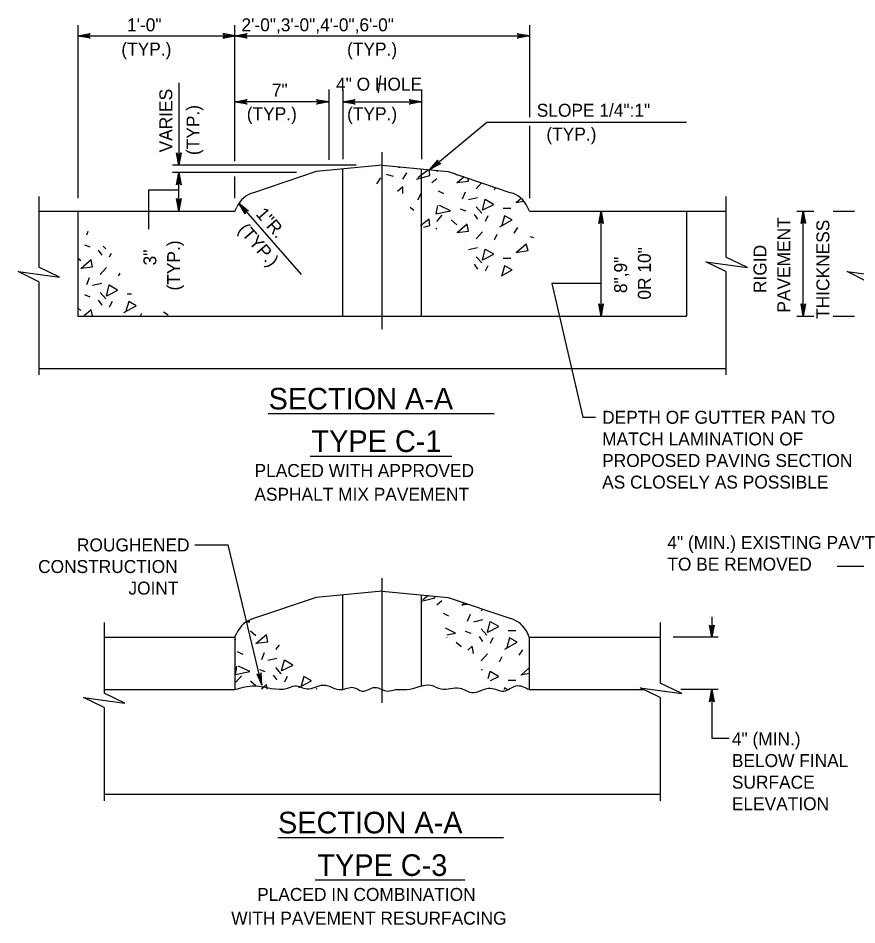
# Model space of a CAD drawing. Extents: x -28.1 to -20.9, y 67 to 77.1.
# Drawn here: x -28.051 to -24.167, y 72.946 to 77.144 of the extents above; entities that cross this region are included whole.
import ezdxf

# ---------------------------------------------------------------- set-up
doc = ezdxf.new("R2010")
doc.units = 0
for name, color, linetype in [('DETL-DIMS', 7, 'Continuous'), ('DETL-LINE', 7, 'Continuous'), ('DETL-NOTE', 7, 'Continuous'), ('DETL-PATT', 7, 'Continuous'), ('DETL-TITL', 7, 'Continuous')]:
    doc.layers.add(name, color=color, linetype=linetype)

msp = doc.modelspace()

# ---------------------------------------------------------------- linework, layer by layer
at = {"layer": 'DETL-DIMS'}
for p, q in [((-27.7744, 77.1109), (-27.7744, 76.3101)), ((-27.0471, 76.4812), (-27.0471, 77.1109)), ((-25.6837, 77.1109), (-25.6837, 76.6848)), ((-27.7744, 77.0612), (-27.0471, 77.0612)), ((-27.0471, 77.0612), (-25.6837, 77.0612)), ((-27.3076, 76.8447), (-27.3076, 76.463)), ((-26.6127, 76.8138), (-26.6127, 76.4872)), ((-26.5472, 76.8138), (-26.5472, 76.4909)), ((-26.1836, 76.8138), (-26.1836, 76.4909)), ((-26.6127, 76.7557), (-27.0471, 76.7557)), ((-26.5472, 76.7557), (-26.1836, 76.7557)), ((-26.1447, 76.4426), (-25.8808, 76.6621)), ((-25.8808, 76.6621), (-24.9559, 76.6621)), ((-25.6837, 76.6457), (-25.6837, 76.3101)), ((-26.3654, 75.704), (-26.3654, 76.5236)), ((-26.4866, 76.463), (-27.3369, 76.463)), ((-26.7619, 76.4285), (-27.3369, 76.4285)), ((-27.3066, 76.2522), (-27.3066, 76.4285)), ((-27.0471, 76.3101), (-27.0471, 76.4104)), ((-27.4468, 76.1665), (-27.4468, 76.3488)), ((-27.4468, 76.3488), (-27.3066, 76.3488)), ((-27.0289, 76.2867), (-26.7405, 75.9569)), ((-25.3519, 75.7646), (-25.3519, 76.2495)), ((-24.4455, 76.2495), (-24.3665, 76.2495)), ((-24.4152, 75.7646), (-24.4152, 76.2495)), ((-24.2764, 76.2495), (-24.1781, 76.2495)), ((-25.3523, 75.9158), (-25.58, 75.9158)), ((-25.58, 75.9158), (-25.436, 75.2959)), ((-24.4455, 75.7646), (-24.3665, 75.7646)), ((-24.2764, 75.7646), (-24.1781, 75.7646)), ((-25.436, 75.2959), (-25.3776, 75.2958)), ((-27.2325, 74.7049), (-27.0788, 74.7049)), ((-26.9226, 74.0556), (-27.0788, 74.7049)), ((-24.1259, 74.6053), (-24.2583, 74.6053)), ((-26.3659, 73.9746), (-26.3659, 74.5518)), ((-24.8393, 74.3726), (-24.8393, 74.2777)), ((-24.809, 74.2777), (-25.0175, 74.2777)), ((-24.809, 74.0352), (-24.9825, 74.0352)), ((-24.8393, 74.0352), (-24.8393, 73.8104)), ((-24.8393, 73.8104), (-24.7588, 73.8104))]:
    msp.add_line(p, q, dxfattribs=at)
for points in [[(-27.7744, 77.0612), (-27.7179, 77.0718), (-27.7223, 77.0688), (-27.7245, 77.065), (-27.7252, 77.0612), (-27.7245, 77.0574), (-27.7223, 77.0536), (-27.7179, 77.0506), (-27.7744, 77.0612), (-27.7223, 77.0536), (-27.7245, 77.0574), (-27.7744, 77.0612), (-27.7252, 77.0612), (-27.7245, 77.065), (-27.7744, 77.0612), (-27.7223, 77.0688)], [(-27.0471, 77.0612), (-27.1036, 77.0718), (-27.0993, 77.0688), (-27.097, 77.065), (-27.0964, 77.0612), (-27.097, 77.0574), (-27.0993, 77.0536), (-27.1036, 77.0506), (-27.0471, 77.0612), (-27.0993, 77.0536), (-27.097, 77.0574), (-27.0471, 77.0612), (-27.0964, 77.0612), (-27.097, 77.065), (-27.0471, 77.0612), (-27.0993, 77.0688)], [(-27.0471, 77.0612), (-26.9907, 77.0718), (-26.995, 77.0688), (-26.9972, 77.065), (-26.9979, 77.0612), (-26.9972, 77.0574), (-26.995, 77.0536), (-26.9907, 77.0506), (-27.0471, 77.0612), (-26.995, 77.0536), (-26.9972, 77.0574), (-27.0471, 77.0612), (-26.9979, 77.0612), (-26.9972, 77.065), (-27.0471, 77.0612), (-26.995, 77.0688)], [(-25.6837, 77.0612), (-25.7402, 77.0506), (-25.7358, 77.0536), (-25.7336, 77.0574), (-25.7329, 77.0612), (-25.7336, 77.065), (-25.7358, 77.0688), (-25.7402, 77.0718), (-25.6837, 77.0612), (-25.7358, 77.0688), (-25.7336, 77.065), (-25.6837, 77.0612), (-25.7329, 77.0612), (-25.7336, 77.0574), (-25.6837, 77.0612), (-25.7358, 77.0536)], [(-27.0471, 76.7557), (-26.9907, 76.7663), (-26.995, 76.7632), (-26.9972, 76.7595), (-26.9979, 76.7557), (-26.9972, 76.7519), (-26.995, 76.7481), (-26.9907, 76.7451), (-27.0471, 76.7557), (-26.995, 76.7481), (-26.9972, 76.7519), (-27.0471, 76.7557), (-26.9979, 76.7557), (-26.9972, 76.7595), (-27.0471, 76.7557), (-26.995, 76.7632)], [(-26.6127, 76.7557), (-26.6691, 76.7451), (-26.6648, 76.7481), (-26.6625, 76.7519), (-26.6619, 76.7557), (-26.6625, 76.7595), (-26.6648, 76.7632), (-26.6691, 76.7663), (-26.6127, 76.7557), (-26.6648, 76.7632), (-26.6625, 76.7595), (-26.6127, 76.7557), (-26.6619, 76.7557), (-26.6625, 76.7519), (-26.6127, 76.7557), (-26.6648, 76.7481)], [(-26.5472, 76.7557), (-26.4907, 76.7663), (-26.4951, 76.7632), (-26.4974, 76.7595), (-26.498, 76.7557), (-26.4974, 76.7519), (-26.4951, 76.7481), (-26.4907, 76.7451), (-26.5472, 76.7557), (-26.4951, 76.7481), (-26.4974, 76.7519), (-26.5472, 76.7557), (-26.498, 76.7557), (-26.4974, 76.7595), (-26.5472, 76.7557), (-26.4951, 76.7632)], [(-26.1836, 76.7557), (-26.2401, 76.7451), (-26.2357, 76.7481), (-26.2335, 76.7519), (-26.2329, 76.7557), (-26.2335, 76.7595), (-26.2357, 76.7632), (-26.2401, 76.7663), (-26.1836, 76.7557), (-26.2357, 76.7632), (-26.2335, 76.7595), (-26.1836, 76.7557), (-26.2329, 76.7557), (-26.2335, 76.7519), (-26.1836, 76.7557), (-26.2357, 76.7481)], [(-27.3076, 76.463), (-27.3182, 76.5195), (-27.3152, 76.5151), (-27.3114, 76.5129), (-27.3076, 76.5122), (-27.3038, 76.5129), (-27.3, 76.5151), (-27.297, 76.5195), (-27.3076, 76.463), (-27.3, 76.5151), (-27.3038, 76.5129), (-27.3076, 76.463), (-27.3076, 76.5122), (-27.3114, 76.5129), (-27.3076, 76.463), (-27.3152, 76.5151)], [(-26.1447, 76.4426), (-26.1081, 76.4869), (-26.1095, 76.4818), (-26.1088, 76.4774), (-26.1069, 76.4741), (-26.1039, 76.4716), (-26.0998, 76.4701), (-26.0945, 76.4706), (-26.1447, 76.4426), (-26.0998, 76.4701), (-26.1039, 76.4716), (-26.1447, 76.4426), (-26.1069, 76.4741), (-26.1088, 76.4774), (-26.1447, 76.4426), (-26.1095, 76.4818)], [(-27.3066, 76.4285), (-27.296, 76.372), (-27.2991, 76.3764), (-27.3029, 76.3787), (-27.3066, 76.3793), (-27.3104, 76.3787), (-27.3142, 76.3764), (-27.3172, 76.372), (-27.3066, 76.4285), (-27.3142, 76.3764), (-27.3104, 76.3787), (-27.3066, 76.4285), (-27.3066, 76.3793), (-27.3029, 76.3787), (-27.3066, 76.4285), (-27.2991, 76.3764)], [(-27.3066, 76.2522), (-27.3172, 76.3087), (-27.3142, 76.3043), (-27.3104, 76.3021), (-27.3066, 76.3014), (-27.3029, 76.3021), (-27.2991, 76.3043), (-27.296, 76.3087), (-27.3066, 76.2522), (-27.2991, 76.3043), (-27.3029, 76.3021), (-27.3066, 76.2522), (-27.3066, 76.3014), (-27.3104, 76.3021), (-27.3066, 76.2522), (-27.3142, 76.3043)], [(-27.0289, 76.2867), (-26.9838, 76.2512), (-26.9889, 76.2525), (-26.9932, 76.2517), (-26.9965, 76.2497), (-26.9989, 76.2467), (-27.0003, 76.2425), (-26.9997, 76.2372), (-27.0289, 76.2867), (-27.0003, 76.2425), (-26.9989, 76.2467), (-27.0289, 76.2867), (-26.9965, 76.2497), (-26.9932, 76.2517), (-27.0289, 76.2867), (-26.9889, 76.2525)], [(-25.3519, 76.2495), (-25.3414, 76.193), (-25.3444, 76.1974), (-25.3481, 76.1996), (-25.3519, 76.2003), (-25.3557, 76.1996), (-25.3595, 76.1974), (-25.3625, 76.193), (-25.3519, 76.2495), (-25.3595, 76.1974), (-25.3557, 76.1996), (-25.3519, 76.2495), (-25.3519, 76.2003), (-25.3481, 76.1996), (-25.3519, 76.2495), (-25.3444, 76.1974)], [(-24.4152, 76.2495), (-24.4046, 76.193), (-24.4076, 76.1974), (-24.4114, 76.1996), (-24.4152, 76.2003), (-24.419, 76.1996), (-24.4228, 76.1974), (-24.4258, 76.193), (-24.4152, 76.2495), (-24.4228, 76.1974), (-24.419, 76.1996), (-24.4152, 76.2495), (-24.4152, 76.2003), (-24.4114, 76.1996), (-24.4152, 76.2495), (-24.4076, 76.1974)], [(-25.3519, 75.7646), (-25.3625, 75.8211), (-25.3595, 75.8168), (-25.3557, 75.8145), (-25.3519, 75.8139), (-25.3481, 75.8145), (-25.3444, 75.8168), (-25.3414, 75.8211), (-25.3519, 75.7646), (-25.3444, 75.8168), (-25.3481, 75.8145), (-25.3519, 75.7646), (-25.3519, 75.8139), (-25.3557, 75.8145), (-25.3519, 75.7646), (-25.3595, 75.8168)], [(-24.4152, 75.7646), (-24.4258, 75.8211), (-24.4228, 75.8168), (-24.419, 75.8145), (-24.4152, 75.8139), (-24.4114, 75.8145), (-24.4076, 75.8168), (-24.4046, 75.8211), (-24.4152, 75.7646), (-24.4076, 75.8168), (-24.4114, 75.8145), (-24.4152, 75.7646), (-24.4152, 75.8139), (-24.419, 75.8145), (-24.4152, 75.7646), (-24.4228, 75.8168)], [(-24.8393, 74.2777), (-24.8499, 74.3341), (-24.8469, 74.3298), (-24.8431, 74.3275), (-24.8393, 74.3269), (-24.8355, 74.3275), (-24.8317, 74.3298), (-24.8287, 74.3341), (-24.8393, 74.2777), (-24.8317, 74.3298), (-24.8355, 74.3275), (-24.8393, 74.2777), (-24.8393, 74.3269), (-24.8431, 74.3275), (-24.8393, 74.2777), (-24.8469, 74.3298)], [(-26.9226, 74.0556), (-26.9255, 74.113), (-26.9274, 74.1081), (-26.9306, 74.105), (-26.9341, 74.1035), (-26.9379, 74.1033), (-26.9421, 74.1046), (-26.9461, 74.1081), (-26.9226, 74.0556), (-26.9421, 74.1046), (-26.9379, 74.1033), (-26.9226, 74.0556), (-26.9341, 74.1035), (-26.9306, 74.105), (-26.9226, 74.0556), (-26.9274, 74.1081)], [(-24.8393, 74.0352), (-24.8287, 73.9788), (-24.8317, 73.9831), (-24.8355, 73.9853), (-24.8393, 73.986), (-24.8431, 73.9853), (-24.8469, 73.9831), (-24.8499, 73.9788), (-24.8393, 74.0352), (-24.8469, 73.9831), (-24.8431, 73.9853), (-24.8393, 74.0352), (-24.8393, 73.986), (-24.8355, 73.9853), (-24.8393, 74.0352), (-24.8317, 73.9831)]]:
    msp.add_lwpolyline(points, dxfattribs=at)
at = {"layer": 'DETL-LINE'}
for p, q in [((-26.3654, 76.463), (-26.671, 76.4335)), ((-26.5472, 75.7646), (-26.5472, 76.4455)), ((-26.3654, 76.463), (-26.0599, 76.4335)), ((-26.1836, 75.7646), (-26.1836, 76.4455)), ((-26.671, 76.4335), (-26.961, 76.3355)), ((-26.0599, 76.4335), (-25.7699, 76.3355)), ((-27.9562, 76.3178), (-27.9562, 75.9902)), ((-24.7746, 76.3178), (-24.7746, 76.0374)), ((-27.9562, 76.2495), (-27.0471, 76.2495)), ((-27.7744, 76.2495), (-27.7744, 75.7646)), ((-27.0471, 76.2495), (-27.0382, 76.2691)), ((-25.6837, 76.2495), (-25.6926, 76.2691)), ((-25.6837, 76.2495), (-24.7746, 76.2495)), ((-24.9564, 76.2495), (-24.9564, 75.7646)), ((-24.7746, 75.9708), (-24.7746, 75.4923)), ((-27.9562, 75.9236), (-27.9562, 75.4923)), ((-27.7744, 75.7646), (-24.9564, 75.7646)), ((-27.9562, 75.5222), (-24.7746, 75.5222)), ((-26.3659, 74.4911), (-26.6715, 74.4617)), ((-26.5477, 74.0354), (-26.5477, 74.4736)), ((-26.3659, 74.4911), (-26.0604, 74.4617)), ((-26.1841, 74.0489), (-26.1841, 74.4736)), ((-26.6715, 74.4617), (-26.9615, 74.3637)), ((-26.0604, 74.4617), (-25.7704, 74.3637)), ((-27.6537, 74.346), (-27.6537, 74.0183)), ((-25.0781, 74.346), (-25.0781, 74.0655)), ((-27.6537, 74.2777), (-27.0476, 74.2777)), ((-27.0476, 74.2777), (-27.0388, 74.2972)), ((-27.0476, 74.2777), (-27.0476, 74.0352)), ((-25.6842, 74.2777), (-25.6931, 74.2972)), ((-25.6842, 74.2777), (-25.0781, 74.2777)), ((-25.6842, 74.2777), (-25.6842, 74.0352)), ((-27.6537, 74.0352), (-27.0476, 74.0352)), ((-25.6842, 74.0352), (-25.1522, 74.0352)), ((-25.0781, 73.999), (-25.0781, 73.5205)), ((-27.6537, 73.9517), (-27.6537, 73.5205)), ((-27.6537, 73.5504), (-25.0781, 73.5504))]:
    msp.add_line(p, q, dxfattribs=at)
for points in [[(-24.7746, 75.9708), (-24.8665, 76.0158), (-24.6743, 75.9896), (-24.7746, 76.0374)], [(-27.9562, 75.9236), (-28.0514, 75.9701), (-27.8592, 75.944), (-27.9562, 75.9902)], [(-24.1175, 75.9236), (-24.2126, 75.9701), (-24.0204, 75.944), (-24.1175, 75.9902)], [(-25.0781, 73.999), (-25.17, 74.0439), (-24.9778, 74.0178), (-25.0781, 74.0655)], [(-27.6537, 73.9517), (-27.7488, 73.9983), (-27.5566, 73.9722), (-27.6537, 74.0183)]]:
    msp.add_lwpolyline(points, dxfattribs=at)
for centre, start, end in [((-26.9279, 76.2189), 105.8409, 155.576), ((-25.803, 76.2189), 24.424, 74.1591), ((-26.9284, 74.2471), 105.8409, 155.576), ((-25.8034, 74.2471), 24.424, 74.1591)]:
    msp.add_arc(centre, 0.1212, start, end, dxfattribs=at)
msp.add_spline([(-27.0476, 74.0352), (-26.9555, 74.0524), (-26.8035, 74.042), (-26.769, 74.0524), (-26.7137, 74.0386), (-26.6377, 74.0559), (-26.5548, 74.0351), (-26.4996, 74.0455), (-26.4581, 74.0282), (-26.3994, 74.0455), (-26.3407, 74.0282), (-26.3027, 74.0351), (-26.2509, 74.0351), (-26.1404, 74.0559), (-26.092, 74.0386), (-26.0057, 74.042), (-25.9504, 74.0213), (-25.8641, 74.042), (-25.8019, 74.0282), (-25.7466, 74.0524), (-25.6842, 74.0352)], degree=3, dxfattribs=at)
at = {"layer": 'DETL-NOTE'}
msp.add_line((-26.3825, 76.7977), (-26.372, 76.8781), dxfattribs=at)
at = {"layer": 'DETL-PATT'}
for p, q in [((-26.4436, 76.4436), (-26.445, 76.4425)), ((-26.2895, 76.4533), (-26.2822, 76.4539)), ((-26.2822, 76.4539), (-26.2822, 76.4539)), ((-26.373, 76.4051), (-26.3922, 76.3762)), ((-26.3473, 76.4212), (-26.3152, 76.4115)), ((-26.2703, 76.3987), (-26.251, 76.4276)), ((-26.1355, 76.3827), (-26.113, 76.4019)), ((-26.113, 76.434), (-26.1094, 76.4381)), ((-26.0239, 76.4214), (-26.02, 76.418)), ((-25.9053, 76.3813), (-25.9301, 76.3538)), ((-25.8406, 76.3595), (-25.8467, 76.3474)), ((-26.1997, 76.3024), (-26.1836, 76.3345)), ((-26.1066, 76.3442), (-26.0809, 76.3313)), ((-25.9815, 76.3377), (-25.9943, 76.3057)), ((-25.9237, 76.3121), (-25.9654, 76.3024)), ((-26.2366, 76.2685), (-26.2189, 76.2543)), ((-26.113, 76.2029), (-26.0874, 76.2318)), ((-26.0039, 76.2607), (-25.9782, 76.2511)), ((-25.9398, 76.235), (-25.9237, 76.2126)), ((-25.9301, 76.2703), (-25.9044, 76.2415)), ((-25.805, 76.2639), (-25.7697, 76.2639)), ((-26.0456, 76.2094), (-26.02, 76.1869)), ((-25.8756, 76.2286), (-25.8884, 76.2029)), ((-27.7288, 76.1556), (-27.7351, 76.1397)), ((-26.1165, 76.1679), (-26.113, 76.1709)), ((-25.9012, 76.1548), (-25.9301, 76.1227)), ((-25.7536, 76.1484), (-25.7376, 76.1741)), ((-25.9815, 76.1067), (-25.9817, 76.1062)), ((-25.8338, 76.142), (-25.8467, 76.1163)), ((-25.6798, 76.1323), (-25.665, 76.1281)), ((-27.7447, 76.0948), (-27.7191, 76.0852)), ((-27.6806, 76.0691), (-27.6645, 76.0467)), ((-27.6568, 76.0885), (-27.6453, 76.0755)), ((-25.9237, 76.081), (-25.9654, 76.0714)), ((-27.7744, 76.0329), (-27.7608, 76.021)), ((-27.6209, 76.0536), (-27.6292, 76.037)), ((-25.9301, 76.0393), (-25.9044, 76.0104)), ((-25.805, 76.0329), (-25.7697, 76.0329)), ((-27.642, 75.9889), (-27.6709, 75.9568)), ((-25.9398, 76.004), (-25.9237, 75.9815)), ((-25.8756, 75.9976), (-25.8884, 75.9719)), ((-27.7223, 75.9408), (-27.7351, 75.9087)), ((-27.5808, 75.9637), (-27.5875, 75.9504)), ((-27.6645, 75.9151), (-27.7062, 75.9054)), ((-27.7447, 75.8637), (-27.7191, 75.8541)), ((-27.6709, 75.8734), (-27.6453, 75.8445)), ((-27.5458, 75.8669), (-27.5257, 75.8669)), ((-27.6806, 75.838), (-27.6645, 75.8156)), ((-27.6164, 75.8316), (-27.6292, 75.806)), ((-27.7744, 75.8018), (-27.7608, 75.7899)), ((-27.4854, 75.7659), (-27.4784, 75.7771)), ((-27.3789, 75.7835), (-27.3564, 75.7707)), ((-26.1124, 74.4282), (-26.0899, 74.4474)), ((-26.0835, 74.3896), (-26.0579, 74.3768)), ((-25.9584, 74.3832), (-25.9712, 74.3511)), ((-25.8997, 74.4074), (-25.907, 74.3993)), ((-25.9006, 74.3576), (-25.9423, 74.3479)), ((-26.9756, 74.3076), (-26.9499, 74.2851)), ((-25.9808, 74.3062), (-25.9552, 74.2966)), ((-25.907, 74.3158), (-25.8814, 74.287)), ((-25.7819, 74.3094), (-25.7466, 74.3094)), ((-27.0476, 74.2651), (-27.043, 74.2691)), ((-26.0648, 74.2767), (-26.0643, 74.2773)), ((-25.9166, 74.2805), (-25.9006, 74.2581)), ((-25.8525, 74.2741), (-25.8653, 74.2484)), ((-26.8421, 74.2408), (-26.8601, 74.2209)), ((-26.0226, 74.2549), (-25.9991, 74.2343)), ((-25.7305, 74.1939), (-25.7145, 74.2196)), ((-27.0366, 74.2113), (-27.0109, 74.1985)), ((-26.9114, 74.2049), (-26.9243, 74.1728)), ((-26.8536, 74.1792), (-26.8954, 74.1696)), ((-25.8781, 74.2003), (-25.907, 74.1682)), ((-25.8107, 74.1875), (-25.8236, 74.1618)), ((-26.8601, 74.1375), (-26.8344, 74.1086)), ((-27.043, 74.0701), (-27.0173, 74.099)), ((-26.9339, 74.1279), (-26.9082, 74.1182)), ((-26.8697, 74.1022), (-26.8536, 74.0797)), ((-26.8055, 74.0958), (-26.8184, 74.0701)), ((-25.9006, 74.1265), (-25.9067, 74.1251)), ((-26.9756, 74.0765), (-26.9499, 74.054)), ((-25.7819, 74.0784), (-25.7466, 74.0784)), ((-26.6703, 74.0367), (-26.6675, 74.0412))]:
    msp.add_line(p, q, dxfattribs=at)
for points in [[(-26.2061, 76.3987), (-26.1451, 76.4148), (-26.1481, 76.4416)], [(-26.1507, 76.4419), (-26.1997, 76.4051)], [(-25.9862, 76.4087), (-26.02, 76.3795)], [(-26.02, 76.3827), (-25.9654, 76.3891), (-25.9681, 76.4025)], [(-26.2703, 76.3316), (-26.2703, 76.3634), (-26.2939, 76.3412)], [(-26.1098, 76.2768), (-26.1163, 76.2383), (-26.0489, 76.2511), (-26.1002, 76.2768)], [(-25.8499, 76.28), (-25.9012, 76.2543), (-25.8884, 76.3057), (-25.8499, 76.2832)], [(-25.7472, 76.2896), (-25.7112, 76.2956)], [(-25.7221, 76.3083), (-25.744, 76.2896)], [(-26.1726, 76.1765), (-26.1451, 76.1837), (-26.1483, 76.2126), (-26.1886, 76.1824)], [(-26.02, 76.1516), (-25.9654, 76.158), (-25.9718, 76.1901), (-26.0186, 76.1495)], [(-25.821, 76.1773), (-25.7632, 76.2094), (-25.7985, 76.2286), (-25.8114, 76.1837)], [(-25.8499, 76.0489), (-25.9012, 76.0232), (-25.8884, 76.0746), (-25.8499, 76.0521)], [(-25.7472, 76.0585), (-25.6894, 76.0682), (-25.6991, 76.097), (-25.744, 76.0585)], [(-27.7608, 75.9857), (-27.7062, 75.9921), (-27.7126, 76.0242), (-27.7608, 75.9825)], [(-25.8124, 75.951), (-25.7632, 75.9783), (-25.7985, 75.9976), (-25.8114, 75.9526)], [(-25.8124, 75.951), (-25.8124, 75.951)], [(-27.5907, 75.883), (-27.642, 75.8573), (-27.6292, 75.9087), (-27.5907, 75.8862)], [(-27.5618, 75.7803), (-27.5041, 75.8124), (-27.5394, 75.8316), (-27.5522, 75.7867)], [(-27.707, 75.7649), (-27.7126, 75.7931), (-27.7454, 75.7648)], [(-26.183, 74.4442), (-26.122, 74.4603), (-26.1229, 74.4677)], [(-26.1503, 74.4703), (-26.1766, 74.4506)], [(-25.9842, 74.436), (-25.9969, 74.425)], [(-25.9969, 74.4282), (-25.9703, 74.4313)], [(-27.001, 74.3451), (-26.9788, 74.3493), (-26.9881, 74.354)], [(-25.8268, 74.3255), (-25.8781, 74.2998), (-25.8653, 74.3511), (-25.8268, 74.3287)], [(-26.0662, 74.2889), (-26.0258, 74.2966), (-26.0726, 74.32)], [(-25.7241, 74.3351), (-25.7217, 74.3355)], [(-26.9499, 74.2498), (-26.8954, 74.2562), (-26.9018, 74.2883), (-26.9499, 74.2466)], [(-25.7979, 74.2228), (-25.7401, 74.2549), (-25.7755, 74.2741), (-25.7883, 74.2292)], [(-25.9458, 74.2031), (-25.9423, 74.2035), (-25.9488, 74.2356), (-25.9689, 74.2181)], [(-26.7798, 74.1471), (-26.8312, 74.1214), (-26.8184, 74.1728), (-26.7798, 74.1503)], [(-27.0398, 74.1439), (-27.0462, 74.1054), (-26.9788, 74.1182), (-27.0301, 74.1439)], [(-25.6842, 74.1355), (-25.7209, 74.104)], [(-26.751, 74.0444), (-26.6932, 74.0765), (-26.7285, 74.0958), (-26.7413, 74.0508)], [(-25.8739, 74.0858), (-25.8653, 74.1201), (-25.8268, 74.0976)], [(-25.8268, 74.0944), (-25.8656, 74.075)], [(-25.7241, 74.104), (-25.6842, 74.1107)], [(-26.8979, 74.0376), (-26.9018, 74.0573), (-26.9243, 74.0377)], [(-25.7858, 74.0359), (-25.7989, 74.0431), (-25.8009, 74.036)]]:
    msp.add_lwpolyline(points, dxfattribs=at)
at = {"layer": 'DETL-TITL'}
for p, q in [((-26.8935, 75.3135), (-25.8469, 75.3135)), ((-26.6994, 75.1165), (-26.0436, 75.1165)), ((-26.8493, 73.351), (-25.8031, 73.351)), ((-26.6755, 73.154), (-25.9833, 73.154))]:
    msp.add_line(p, q, dxfattribs=at)

# ---------------------------------------------------------------- texts
at = {"layer": 'DETL-NOTE'}
for s, p in [('1\'-0"', (-27.5471, 77.0828)), ('2\'-0",3\'-0",4\'-0",6\'-0"', (-27.017, 77.0828)), ('(TYP.)', (-27.5734, 76.9706)), ('(TYP.)', (-26.528, 76.9706)), ('4" O HOLE', (-26.5792, 76.8079)), ('7"', (-26.8762, 76.7803)), ('(TYP.)', (-26.9925, 76.6711)), ('(TYP.)', (-26.528, 76.6711)), ('SLOPE 1/4":1"', (-25.6496, 76.6871)), ('  (TYP.) ', (-25.6496, 76.5771)), ('DEPTH OF GUTTER PAN TO', (-25.3468, 75.2658)), ('MATCH LAMINATION OF', (-25.3468, 75.1658)), ('PROPOSED PAVING SECTION', (-25.3468, 75.0658)), ('PLACED WITH APPROVED', (-26.9565, 75.0194)), ('AS CLOSELY AS POSSIBLE', (-25.3468, 74.9658)), ('ASPHALT MIX PAVEMENT', (-26.9573, 74.9094)), ('ROUGHENED', (-27.7789, 74.6749)), ('4" (MIN.) EXISTING PAV\'T', (-25.0448, 74.6859)), ('CONSTRUCTION', (-27.9589, 74.5749)), ('TO BE REMOVED', (-25.0448, 74.5859)), ('JOINT', (-27.5405, 74.4749)), ('4" (MIN.)', (-24.746, 73.7766)), ('BELOW FINAL', (-24.746, 73.6766)), ('SURFACE', (-24.746, 73.5766)), ('ELEVATION', (-24.746, 73.4766)), ('PLACED IN COMBINATION', (-26.9445, 73.0569)), ('WITH PAVEMENT RESURFACING', (-27.0645, 72.9469))]:
    msp.add_text(s, height=0.06, dxfattribs=at).set_placement(p)
for s, rotation, p in [('VARIES', 90, (-27.3374, 76.522)), ('(TYP.)', 90, (-27.2116, 76.5097)), ('1"R.', 311.1703, (-26.9537, 76.2344)), ('(TYP.)', 311.1703, (-27.0365, 76.162)), ('PAVEMENT', 90, (-24.4758, 75.7803)), ('THICKNESS', 90, (-24.2946, 75.7513)), ('(TYP.)', 90, (-27.3012, 75.8827)), ('3"', 90, (-27.4112, 75.9989)), ('0R 10"', 90, (-25.1213, 75.8407)), ('RIGID', 90, (-24.5858, 75.8711)), ('8",9"', 90, (-25.2313, 75.8707))]:
    msp.add_text(s, height=0.06, rotation=rotation, dxfattribs=at).set_placement(p)
at = {"layer": 'DETL-TITL'}
for s, p in [('SECTION A-A', (-26.8914, 75.3321)), ('TYPE C-1', (-26.6927, 75.1351)), ('SECTION A-A', (-26.8478, 73.3696)), ('TYPE C-3', (-26.6657, 73.1726))]:
    msp.add_text(s, height=0.1, dxfattribs=at).set_placement(p)

doc.saveas('drawing.dxf')
